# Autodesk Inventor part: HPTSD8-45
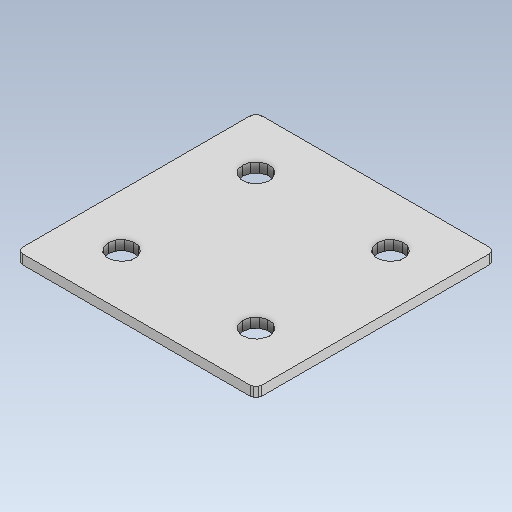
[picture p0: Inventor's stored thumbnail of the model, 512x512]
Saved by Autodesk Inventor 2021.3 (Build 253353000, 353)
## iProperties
Created: 2022-02
Part Number: HPTSD8-45
Material: 一般
Document SubType Name: Modeling
Designer: kengo
Density: 1 g/cm^3
Appearance: 既定
Author: kengo
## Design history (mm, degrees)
feature "HPTSD8-45"
node "ソリッド1"
